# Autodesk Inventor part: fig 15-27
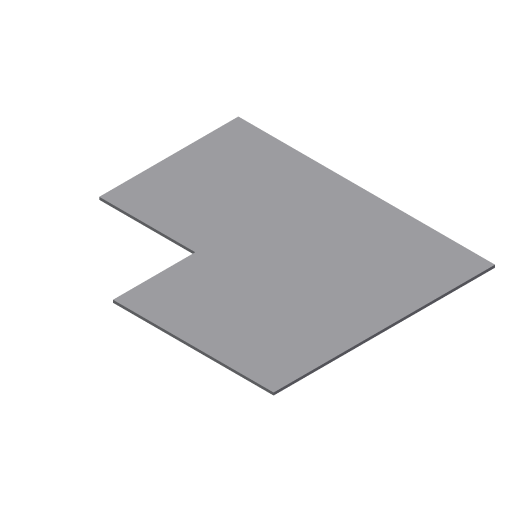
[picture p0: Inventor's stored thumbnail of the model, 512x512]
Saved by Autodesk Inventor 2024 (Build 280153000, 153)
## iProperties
Created: 2005-03
Part Number: fig 15-27
Document SubType Name: Sheet Metal
Designer: CADCIM
Manufacturer: Standard
Standards Organization: Custom
Density: 1 g/cm^3
Sheet Metal Rule: Default
Material: Generic
Appearance: Default
Author: CADCIM
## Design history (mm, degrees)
node "Face1"
  sketch "Sketch1"
    geometry: L1 (29.25, 32.25)-(-19.875, 32.25); L2 (-19.875, 32.25)-(-19.875, 5.625); L3 (-19.875, 5.625)-(-1.5, 5.625); L4 (-1.5, 5.625)-(-1.5, -10.125); L5 (-1.5, -10.125)-(29.25, -10.125); L6 (29.25, -10.125)-(29.25, 32.25)
    constraints: 12 end point, 4 parallel, 1 horizontal, 1 perpendicular
body "Solid1"
face "Plate1" dims "d1" = 0.5 (= Thickness)
other parameters: "Thickness" = 0.5, "BendRadius" = 0.5 (= Thickness), "BendReliefWidth" = 0.5 (= Thickness), "BendReliefDepth" = 0.25 (= 0.5 x Thickness), "CornerReliefSize" = 2 (= 4 x Thickness), "SeamGap" = 0.01, "MinimumRemnant" = 1 (= 2 x Thickness), "TransitionRadius" = 0.5 (= BendRadius), "JacobiRadiusSize" = 0.5 (= Thickness), "GapSize" = 0.5 (= Thickness), "d0" = 0.5 (= BendRadius)
